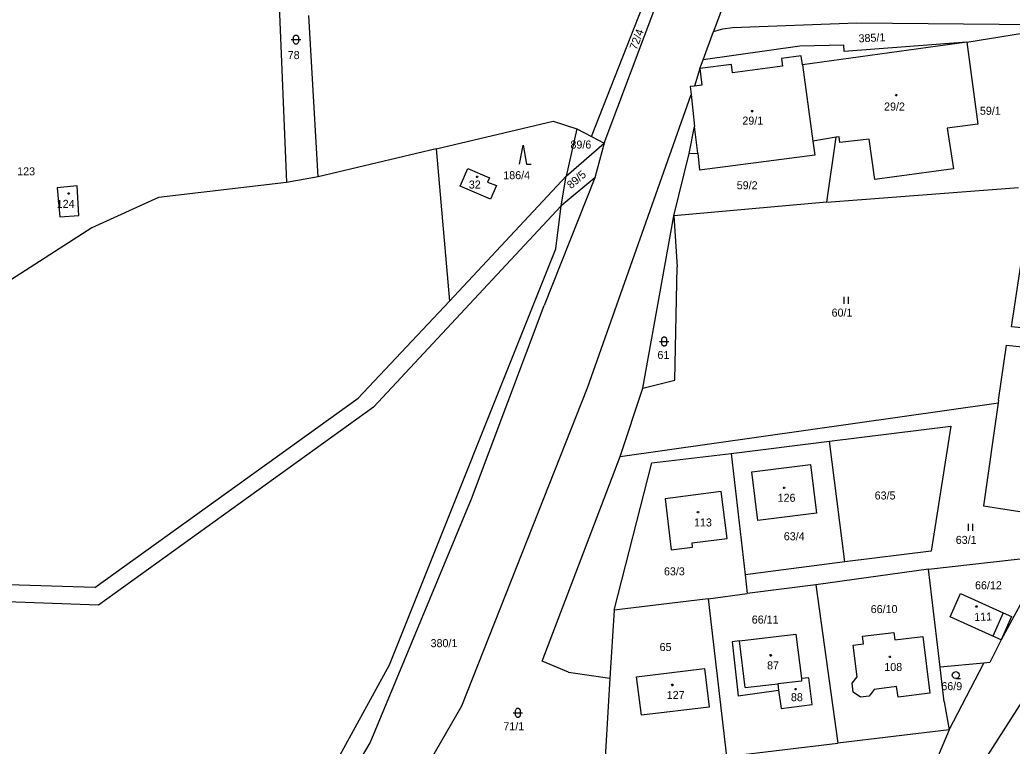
# Model space of a CAD drawing. Extents: x -811039 to -805820, y -1161436 to -1155864.
# Drawn here: x -806771.7 to -806560.9, y -1158135.7 to -1157981.5 of the extents above; entities that cross this region are included whole.
import ezdxf

# ---------------------------------------------------------------- set-up
doc = ezdxf.new("R2010")
doc.units = 0
for name, color, linetype in [('Default', 7, 'Continuous'), ('KN_HRANICE', 7, 'Continuous'), ('KN_KULTURY', 7, 'Continuous'), ('KN_PARCELY', 7, 'Continuous'), ('KN_SLUCKY', 7, 'Continuous')]:
    doc.layers.add(name, color=color, linetype=linetype)

# ---------------------------------------------------------------- blocks, each defined once
blk = doc.blocks.new('304')
at = {"layer": 'Default'}
blk.add_lwpolyline([(0, 0), (-0.38, 0.1), (-0.65, 0.37), (-0.75, 0.74), (-0.65, 1.11), (-0.38, 1.38), (-0.01, 1.48), (0.36, 1.38), (0.63, 1.11), (0.73, 0.73), (0.63, 0.35), (0.36, 0.08), (-0.02, -0.02), (0.98, -0.02)], dxfattribs=at)
blk = doc.blocks.new('306')
at = {"layer": 'Default'}
for p, q in [((-0.5, 1.5), (-0.5, 0)), ((0.5, 0), (0.5, 1.5))]:
    blk.add_line(p, q, dxfattribs=at)
blk = doc.blocks.new('308')
at = {"layer": 'Default'}
blk.add_lwpolyline([(-0.75, 0), (0, 4), (0.75, 0), (1.75, 0)], dxfattribs=at)
blk = doc.blocks.new('316')
at = {"layer": 'Default'}
for points in [[(-1, 1), (0.27, 1), (1, 1)], [(-0.5, 1.5), (-0.4, 1.79), (-0.15, 1.97), (0.16, 1.97), (0.41, 1.79), (0.51, 1.5), (0.51, 0.5), (0.41, 0.21), (0.16, 0.03), (-0.15, 0.03), (-0.4, 0.21), (-0.5, 0.5), (-0.5, 1.5)]]:
    blk.add_lwpolyline(points, dxfattribs=at)
blk = doc.blocks.new('402')
at = {"layer": 'Default'}
blk.add_lwpolyline([(0.09, 0.15), (0.18, 0), (0.09, -0.15), (-0.09, -0.15), (-0.18, 0), (-0.09, 0.15), (0.09, 0.15)], dxfattribs=at)

msp = doc.modelspace()

# ---------------------------------------------------------------- linework, layer by layer
at = {"layer": 'KN_HRANICE'}
for p, q in [((-806650.25, -1158006.25), (-806630.4, -1157955.86)), ((-806618.72, -1157968.82), (-806624.34, -1157983.98)), ((-806716.77, -1157975.04), (-806715.04, -1158016)), ((-806647.57, -1158007.68), (-806636.14, -1157977.4)), ((-806708.29, -1158014.83), (-806710.29, -1157980.53)), ((-806622.35, -1157983.37), (-806620.27, -1157983.09)), ((-806620.27, -1157983.09), (-806593.91, -1157982.13)), ((-806593.91, -1157982.13), (-806547.55, -1157982.51)), ((-806570.5, -1157986.22), (-806547.55, -1157982.51)), ((-806626.56, -1157989.99), (-806624.34, -1157983.98)), ((-806624.34, -1157983.98), (-806622.35, -1157983.37)), ((-806605.97, -1157987.04), (-806626.56, -1157989.99)), ((-806596.64, -1157986.83), (-806605.97, -1157987.04)), ((-806570.5, -1157986.22), (-806605.46, -1157991.06)), ((-806596.57, -1157988.21), (-806596.64, -1157986.83)), ((-806570.5, -1157986.22), (-806596.57, -1157988.21)), ((-806570.5, -1157986.22), (-806568.17, -1158003.62)), ((-806627.24, -1157991.82), (-806626.56, -1157989.99)), ((-806605.46, -1157991.06), (-806603.27, -1158007.25)), ((-806627.24, -1157991.82), (-806628.4, -1157995.55)), ((-806628.4, -1157995.55), (-806629.31, -1157995.65)), ((-806629.31, -1157995.65), (-806629.11, -1157997.36)), ((-806651.08, -1158059.61), (-806629.11, -1157997.36)), ((-806629.11, -1157997.36), (-806628.34, -1158004.14)), ((-806683.24, -1158008.88), (-806658.37, -1158003)), ((-806658.37, -1158003), (-806653.36, -1158004.59)), ((-806629.49, -1158009.85), (-806628.34, -1158004.14)), ((-806568.17, -1158003.62), (-806574.68, -1158004.5)), ((-806653.36, -1158004.59), (-806655.66, -1158014.66)), ((-806653.36, -1158004.59), (-806650.25, -1158006.25)), ((-806650.25, -1158006.25), (-806647.57, -1158007.68)), ((-806598.29, -1158006.41), (-806603.27, -1158007.25)), ((-806600.28, -1158020.19), (-806598.29, -1158006.41)), ((-806597.67, -1158006.3), (-806598.29, -1158006.41)), ((-806597.53, -1158007.53), (-806597.67, -1158006.3)), ((-806574.68, -1158004.5), (-806573.37, -1158013.12)), ((-806655.66, -1158014.66), (-806647.57, -1158007.68)), ((-806647.57, -1158007.68), (-806649.57, -1158015.03)), ((-806603.27, -1158007.25), (-806602.78, -1158010.18)), ((-806591.24, -1158006.79), (-806597.53, -1158007.53)), ((-806590.06, -1158015.35), (-806591.24, -1158006.79)), ((-806683.24, -1158008.88), (-806708.29, -1158014.83)), ((-806683.24, -1158008.88), (-806680.42, -1158041.23)), ((-806632.78, -1158023.07), (-806629.49, -1158009.85)), ((-806629.49, -1158009.85), (-806627.69, -1158009.82)), ((-806627.69, -1158009.82), (-806627.28, -1158013.43)), ((-806602.78, -1158010.18), (-806627.28, -1158013.43)), ((-806708.29, -1158014.83), (-806715.04, -1158016)), ((-806655.66, -1158014.66), (-806680.42, -1158041.23)), ((-806678.15, -1158016.79), (-806676.53, -1158013.05)), ((-806676.53, -1158013.05), (-806671.94, -1158015.04)), ((-806656.73, -1158020.99), (-806655.66, -1158014.66)), ((-806573.37, -1158013.12), (-806590.06, -1158015.35)), ((-806759.54, -1158016.7), (-806763.74, -1158017.18)), ((-806759.18, -1158023), (-806759.54, -1158016.7)), ((-806715.04, -1158016), (-806742.23, -1158019.17)), ((-806671.73, -1158019.53), (-806678.15, -1158016.79)), ((-806671.94, -1158015.04), (-806672.35, -1158015.95)), ((-806672.35, -1158015.95), (-806670.44, -1158016.66)), ((-806670.44, -1158016.66), (-806671.73, -1158019.53)), ((-806649.57, -1158015.03), (-806660.29, -1158042.1)), ((-806649.57, -1158015.03), (-806656.73, -1158020.99)), ((-806763.74, -1158017.18), (-806763.22, -1158023.33)), ((-806600.28, -1158020.19), (-806559.56, -1158017.1)), ((-806742.23, -1158019.17), (-806756.36, -1158025.64)), ((-806696.59, -1158063.72), (-806656.73, -1158020.99)), ((-806657.82, -1158030.08), (-806656.73, -1158020.99)), ((-806600.28, -1158020.19), (-806632.78, -1158023.07)), ((-806561.02, -1158046.66), (-806556.99, -1158020.02)), ((-806763.22, -1158023.33), (-806759.18, -1158023)), ((-806639.36, -1158059.7), (-806632.78, -1158023.07)), ((-806632.78, -1158023.07), (-806632.07, -1158033.91)), ((-806756.36, -1158025.64), (-806779.2, -1158040.26)), ((-806693.13, -1158118.44), (-806657.82, -1158030.08)), ((-806632.57, -1158057.99), (-806632.07, -1158033.91)), ((-806699.85, -1158061.84), (-806680.42, -1158041.23)), ((-806675.76, -1158083.19), (-806660.29, -1158042.1)), ((-806535.38, -1158049.27), (-806561.02, -1158046.66)), ((-806563.8, -1158062.27), (-806562.08, -1158050.54)), ((-806562.08, -1158050.54), (-806536.5, -1158053.32)), ((-806639.36, -1158059.7), (-806632.57, -1158057.99)), ((-806677.82, -1158127.15), (-806651.08, -1158059.61)), ((-806644.16, -1158074.21), (-806639.36, -1158059.7)), ((-806755.75, -1158102.03), (-806699.85, -1158061.84)), ((-806644.16, -1158074.21), (-806564.76, -1158062.95)), ((-806563.88, -1158062.82), (-806566.96, -1158084.66)), ((-806564.76, -1158062.95), (-806563.88, -1158062.82)), ((-806563.8, -1158062.27), (-806563.88, -1158062.82)), ((-806696.59, -1158063.72), (-806754.99, -1158105.78)), ((-806599.72, -1158070.98), (-806573.94, -1158067.75)), ((-806573.94, -1158067.75), (-806578.11, -1158094.28)), ((-806620.58, -1158073.54), (-806599.72, -1158070.98)), ((-806596.44, -1158096.58), (-806599.72, -1158070.98)), ((-806637.41, -1158075.58), (-806620.58, -1158073.54)), ((-806620.58, -1158073.54), (-806617.63, -1158099.35)), ((-806660.71, -1158117.63), (-806644.16, -1158074.21)), ((-806645.47, -1158106.82), (-806637.41, -1158075.58)), ((-806616.21, -1158077.45), (-806603.76, -1158075.89)), ((-806603.76, -1158075.89), (-806602.48, -1158086.22)), ((-806614.92, -1158087.77), (-806616.21, -1158077.45)), ((-806622.68, -1158081.65), (-806634.58, -1158083.17)), ((-806621.43, -1158091.62), (-806622.68, -1158081.65)), ((-806697.27, -1158135.03), (-806675.76, -1158083.19)), ((-806634.58, -1158083.17), (-806633.31, -1158094)), ((-806602.48, -1158086.22), (-806614.92, -1158087.77)), ((-806566.96, -1158084.66), (-806551.02, -1158087.22)), ((-806628.88, -1158092.55), (-806621.43, -1158091.62)), ((-806628.77, -1158093.44), (-806628.88, -1158092.55)), ((-806633.31, -1158094), (-806628.77, -1158093.44)), ((-806578.11, -1158094.28), (-806596.44, -1158096.58)), ((-806596.44, -1158096.58), (-806617.63, -1158099.35)), ((-806578.67, -1158098.14), (-806553.63, -1158095.33)), ((-806553.63, -1158095.33), (-806563.21, -1158113.11)), ((-806578.67, -1158098.14), (-806602.6, -1158101.43)), ((-806576.22, -1158118.97), (-806578.67, -1158098.14)), ((-806755.75, -1158102.03), (-806826.2, -1158099.73)), ((-806617.63, -1158099.35), (-806617.15, -1158103.27)), ((-806754.99, -1158105.78), (-806823.76, -1158103.31)), ((-806625.5, -1158104.42), (-806617.15, -1158103.27)), ((-806602.6, -1158101.43), (-806617.15, -1158103.27)), ((-806602.6, -1158101.43), (-806597.92, -1158135.1)), ((-806574.04, -1158108.24), (-806571.85, -1158103.3)), ((-806571.85, -1158103.3), (-806562.79, -1158107.37)), ((-806625.5, -1158104.42), (-806645.47, -1158106.82)), ((-806625.5, -1158104.42), (-806621.6, -1158137.92)), ((-806645.47, -1158106.82), (-806646.33, -1158121.28)), ((-806562.79, -1158107.37), (-806561.02, -1158108.21)), ((-806564.99, -1158112.33), (-806574.04, -1158108.24)), ((-806561.02, -1158108.21), (-806563.21, -1158113.11)), ((-806592.69, -1158112.36), (-806586, -1158111.55)), ((-806586, -1158111.55), (-806585.79, -1158113.16)), ((-806618.83, -1158113.37), (-806620.39, -1158113.54)), ((-806620.39, -1158113.54), (-806619.09, -1158125.02)), ((-806618.83, -1158113.37), (-806606.85, -1158111.91)), ((-806606.85, -1158111.91), (-806605.66, -1158121.36)), ((-806592.49, -1158114), (-806592.69, -1158112.36)), ((-806585.79, -1158113.16), (-806579.88, -1158112.41)), ((-806579.88, -1158112.41), (-806578.35, -1158124.49)), ((-806563.21, -1158113.11), (-806565.64, -1158117.94)), ((-806563.21, -1158113.11), (-806564.99, -1158112.33)), ((-806594.69, -1158114.28), (-806592.49, -1158114)), ((-806593.85, -1158120.96), (-806594.69, -1158114.28)), ((-806655.15, -1158119.99), (-806660.71, -1158117.63)), ((-806566.94, -1158118.07), (-806576.22, -1158118.97)), ((-806574.25, -1158132.24), (-806566.94, -1158118.07)), ((-806565.64, -1158117.94), (-806566.94, -1158118.07)), ((-806723.74, -1158174.06), (-806693.13, -1158118.44)), ((-806655.15, -1158119.99), (-806646.33, -1158121.28)), ((-806640.69, -1158120.97), (-806626.23, -1158119.19)), ((-806626.23, -1158119.19), (-806625.27, -1158127.43)), ((-806575.35, -1158126.31), (-806576.22, -1158118.97)), ((-806646.33, -1158121.28), (-806647.48, -1158140.75)), ((-806639.65, -1158129.1), (-806640.69, -1158120.97)), ((-806605.64, -1158121.92), (-806610.66, -1158122.49)), ((-806604.07, -1158121.2), (-806605.66, -1158121.36)), ((-806605.66, -1158121.36), (-806605.64, -1158121.92)), ((-806603.4, -1158126.84), (-806604.07, -1158121.2)), ((-806594.87, -1158122.36), (-806593.85, -1158120.96)), ((-806594.66, -1158124.22), (-806594.87, -1158122.36)), ((-806619.09, -1158125.02), (-806610.53, -1158123.85)), ((-806610.66, -1158122.49), (-806610.53, -1158123.85)), ((-806610.53, -1158123.85), (-806609.99, -1158127.72)), ((-806593.12, -1158125.33), (-806594.66, -1158124.22)), ((-806590.21, -1158123.68), (-806591.24, -1158125.1)), ((-806585.43, -1158123.05), (-806590.21, -1158123.68)), ((-806585.1, -1158125.31), (-806585.43, -1158123.05)), ((-806578.35, -1158124.49), (-806585.1, -1158125.31)), ((-806591.24, -1158125.1), (-806593.12, -1158125.33)), ((-806575.35, -1158126.31), (-806574.25, -1158132.24)), ((-806558.78, -1158126.18), (-806568.02, -1158140.53)), ((-806718.26, -1158196.99), (-806677.82, -1158127.15)), ((-806625.27, -1158127.43), (-806639.65, -1158129.1)), ((-806609.99, -1158127.72), (-806603.4, -1158126.84)), ((-806574.25, -1158132.24), (-806597.92, -1158135.1)), ((-806574.25, -1158132.24), (-806577.2, -1158139.11)), ((-806721.04, -1158174.85), (-806697.27, -1158135.03)), ((-806621.6, -1158137.92), (-806597.92, -1158135.1))]:
    msp.add_line(p, q, dxfattribs=at)
at = {"layer": 'KN_SLUCKY'}
for p, q in [((-806605.73, -1157989.14), (-806609.88, -1157989.69)), ((-806605.46, -1157991.06), (-806605.73, -1157989.14)), ((-806620.5, -1157990.95), (-806627.24, -1157991.82)), ((-806620.28, -1157992.72), (-806620.5, -1157990.95)), ((-806609.66, -1157991.3), (-806620.28, -1157992.72)), ((-806609.88, -1157989.69), (-806609.66, -1157991.3)), ((-806627.24, -1157991.82), (-806626.81, -1157995.37)), ((-806626.81, -1157995.37), (-806628.4, -1157995.55)), ((-806627.69, -1158009.82), (-806628.34, -1158004.14)), ((-806562.79, -1158107.37), (-806564.99, -1158112.33)), ((-806617.6, -1158123.27), (-806618.83, -1158113.37)), ((-806617.6, -1158123.27), (-806610.66, -1158122.49))]:
    msp.add_line(p, q, dxfattribs=at)

# ---------------------------------------------------------------- block references
at = {"layer": 'KN_KULTURY'}
for name, p in [('316', (-806713.03, -1157986.67)), ('402', (-806585.53, -1157997.47)), ('402', (-806616.12, -1158000.84)), ('308', (-806664.8, -1158012.1)), ('402', (-806674.55, -1158014.79)), ('402', (-806761.34, -1158018.33)), ('306', (-806596.13, -1158041.79)), ('316', (-806634.82, -1158050.79)), ('402', (-806609.33, -1158080.84)), ('402', (-806627.61, -1158086.02)), ('306', (-806569.76, -1158090.02)), ('402', (-806568.47, -1158106.06)), ('402', (-806612.17, -1158116.43)), ('402', (-806586.87, -1158116.75)), ('304', (-806572.86, -1158121.35)), ('402', (-806633.05, -1158122.73)), ('402', (-806606.91, -1158123.63)), ('316', (-806665.89, -1158129.64))]:
    msp.add_blockref(name, p, dxfattribs=at)

# ---------------------------------------------------------------- texts
at = {"layer": 'KN_PARCELY'}
for s, rotation, p in [('72/4', 69.5, (-806640.65, -1157987.98)), ('385/1', 2.636, (-806593.48, -1157986.27)), ('89/5', 40.795, (-806654.58, -1158017.47)), ('111', 1.833, (-806568.92, -1158109.13))]:
    msp.add_text(s, height=1.7, rotation=rotation, dxfattribs=at).set_placement(p)
for s, p in [('78', (-806714.78, -1157989.81)), ('29/2', (-806588.1, -1158000.73)), ('59/1', (-806567.74, -1158001.63)), ('29/1', (-806618.2, -1158003.72)), ('89/6', (-806654.72, -1158008.81)), ('123', (-806772.25, -1158014.5)), ('186/4', (-806668.99, -1158015.31)), ('32', (-806676.31, -1158017.3)), ('59/2', (-806619.4, -1158017.45)), ('124', (-806763.85, -1158021.4)), ('60/1', (-806599.25, -1158044.49)), ('61', (-806636.24, -1158053.49)), ('126', (-806610.71, -1158083.82)), ('63/5', (-806590.1, -1158083.33)), ('113', (-806628.47, -1158089.06)), ('63/4', (-806609.4, -1158091.99)), ('63/1', (-806572.88, -1158092.76)), ('63/3', (-806634.86, -1158099.44)), ('66/12', (-806568.78, -1158102.4)), ('66/10', (-806590.94, -1158107.46)), ('66/11', (-806616.21, -1158109.68)), ('380/1', (-806684.43, -1158114.69)), ('65', (-806635.79, -1158115.51)), ('87', (-806612.96, -1158119.4)), ('108', (-806588.05, -1158119.74)), ('66/9', (-806575.94, -1158123.82)), ('127', (-806634.27, -1158125.7)), ('88', (-806607.89, -1158126.16)), ('71/1', (-806668.97, -1158132.34))]:
    msp.add_text(s, height=1.7, dxfattribs=at).set_placement(p)

doc.saveas('drawing.dxf')
